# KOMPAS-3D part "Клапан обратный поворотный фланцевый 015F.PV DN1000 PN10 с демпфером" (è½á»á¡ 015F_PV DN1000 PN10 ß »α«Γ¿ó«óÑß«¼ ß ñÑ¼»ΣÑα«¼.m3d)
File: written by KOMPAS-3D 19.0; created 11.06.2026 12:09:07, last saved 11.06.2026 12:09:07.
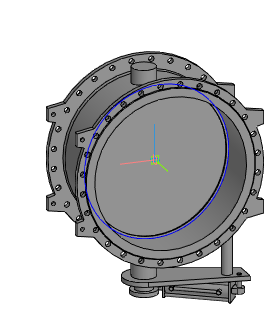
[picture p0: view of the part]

Document properties: Автор: Энергия; Полное имя файла: Z:\3.Личные\kachalov\001_3d для проектировщиков\5.5 Тип 015F.PV Клапан обратный поворотный с двумя эксцентриками\_stp_Клапан 015F.PV DN300-DN1200 с противовесом с демпфером\Клапан 015F_PV DN1000 PN10 с противовесом с демпфером.m3d

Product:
- Part/product: Клапан обратный поворотный фланцевый 015F.PV DN1000 PN10 с демпфером

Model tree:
1. Операция без истории:1
2. Сплайн:1
     Координата Y = 30; Координата Z = 500; Вес = 1; Координата X = 1000; Координата Y = 161.652; Координата Z = 500; Вес = 0.333333; Координата X = 1000; Координата Y = 161.652; Координата Z = -500; Вес = 0.333333; Координата Y = 30; Координата Z = -500; Вес = 1; Координата X = -1000; Координата Y = -101.652; Координата Z = -500; Вес = 0.333333; Координата X = -1000; Координата Y = -101.652; Координата Z = 500; Вес = 0.333333; Порядок = 4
